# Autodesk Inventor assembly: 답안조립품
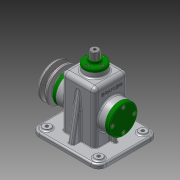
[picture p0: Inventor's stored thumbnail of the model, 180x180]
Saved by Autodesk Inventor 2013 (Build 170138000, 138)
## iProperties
Created: 2016-01
Part Number: 답안조립품
Document SubType Name: Assembly
Designer: User
Author: User
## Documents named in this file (19)
- C:\Users\User\Desktop\460126V1016\답안조립품.iam
- C:\Users\User\Desktop\460126V1016\본체.ipt
- C:\Users\User\Desktop\460126V1016\뒤커버.ipt
- C:\Users\User\Desktop\460126V1016\앞커버.ipt
- C:\Users\User\Desktop\460126V1016\편심축.ipt
- C:\Users\User\Desktop\460126V1016\볼트 M4 x 10.ipt
- C:\Users\User\Desktop\460126V1016\베어링 15 x 35 x 11.ipt
- C:\Users\User\Desktop\460126V1016\V-벨트풀리.ipt
- C:\Users\User\Desktop\460126V1016\키 5 x 5 x 14.ipt
- C:\Users\User\Desktop\460126V1016\볼트 M6 x 12.ipt
- C:\Users\User\Desktop\460126V1016\상부부시.ipt
- C:\Users\User\Desktop\460126V1016\오일실 15 25 7.ipt
- C:\Users\User\Desktop\460126V1016\볼트 M3 x 8.ipt
- C:\Users\User\Desktop\460126V1016\멈춤링 15 x 1.ipt
- C:\Users\User\Desktop\460126V1016\멈춤링 6 x 5.ipt
- C:\Users\User\Desktop\460126V1016\와셔.ipt
- C:\Users\User\Desktop\460126V1016\슬라이드바.ipt
- C:\Users\User\Desktop\460126V1016\고정핀.ipt
- C:\Users\User\Desktop\460126V1016\링크.ipt
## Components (15 placed, 5 different names)
1. V-벨트풀리:1
2. ISO 4018 M6 x 12:1
3. 고정핀:1
4. ISO 4762 M4 x 10:1
5. ISO 4762 M4 x 10:3
6. ISO 4762 M4 x 10:4
7. ISO 4762 M4 x 10:5
8. ISO 4762 M4 x 10:2
9. ISO 4762 M4 x 10:6
10. ISO 4762 M4 x 10:7
11. ISO 4762 M4 x 10:8
12. ISO 4762 M3 x 8:1
13. ISO 4762 M3 x 8:2
14. ISO 4762 M3 x 8:3
15. ISO 4762 M3 x 8:4
